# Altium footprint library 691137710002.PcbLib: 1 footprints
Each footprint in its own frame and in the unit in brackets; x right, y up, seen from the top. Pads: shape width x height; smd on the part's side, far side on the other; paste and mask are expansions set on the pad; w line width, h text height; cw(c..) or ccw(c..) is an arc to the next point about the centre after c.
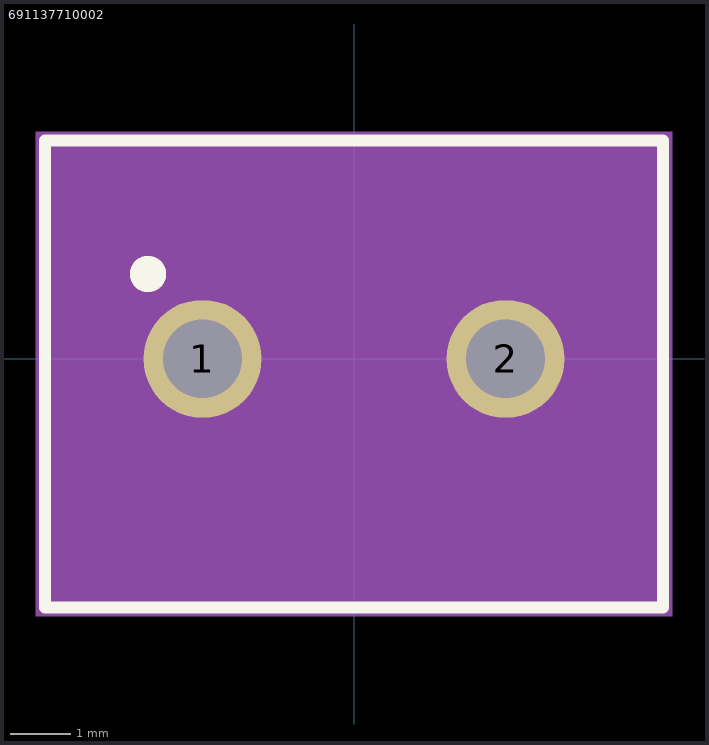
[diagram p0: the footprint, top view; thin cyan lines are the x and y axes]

## 691137710002 [mm]
pads (2):
  round 1.95 hole 1.3: 1(-2.5,0) 2(2.5,0)
Top Overlay:
  circle w0.4: c-3.4,1.4 r0.1
  lines w0.2: -5.1,-4.1 5.1,-4.1 5.1,3.6 -5.1,3.6 -5.1,-4.1
Assembly Top:
  lines w0.1: -5,-4 5,-4 5,3.5 -5,3.5 -5,-4
Courtyard Top:
  region: 5.25,-4.25 -5.25,-4.25 -5.25,3.75 5.25,3.75
3D body "step_temp.STEP": height 11.5, standoff -3.6, extent -4.746,-2.921 5.254,4.579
